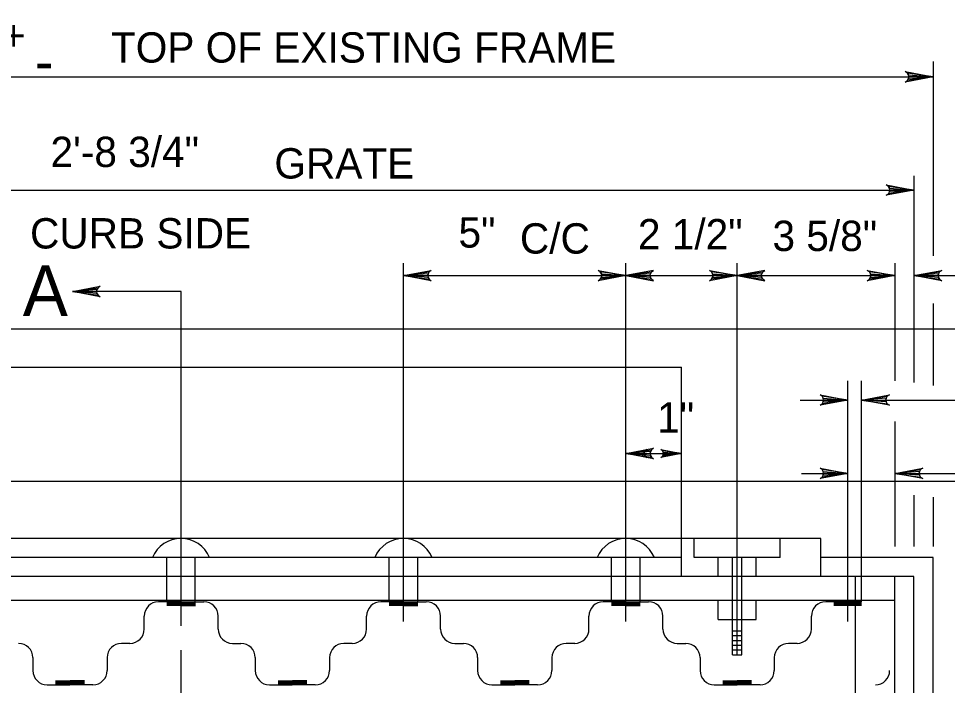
# Model space of a CAD drawing. Extents: x -0.3 to 6.9, y -6.5 to 3.5.
# Drawn here: x 2.615 to 4.451, y 2.033 to 3.352 of the extents above; entities that cross this region are included whole.
import ezdxf

# ---------------------------------------------------------------- set-up
doc = ezdxf.new("R2010")
doc.units = 0
for name, color, linetype in [('DETL-DIMS', 7, 'Continuous'), ('DETL-LINE', 7, 'Continuous'), ('DETL-NOTE', 7, 'Continuous'), ('DETL-PATT', 7, 'Continuous')]:
    doc.layers.add(name, color=color, linetype=linetype)

msp = doc.modelspace()

# ---------------------------------------------------------------- linework, layer by layer
at = {"layer": 'DETL-DIMS'}
for p, q in [((4.4228, 3.2671), (4.4228, 2.8829)), ((1.4487, 3.2371), (4.4228, 3.2371)), ((4.3851, 3.0414), (4.3851, 2.6324)), ((1.4863, 3.013), (4.3851, 3.013)), ((3.3762, 2.1596), (3.3762, 2.8683)), ((3.8157, 2.1596), (3.8157, 2.8683)), ((4.0357, 2.0942), (4.0357, 2.8683)), ((4.3475, 2.8683), (4.3475, 2.6361)), ((3.3762, 2.844), (4.3475, 2.844)), ((4.3851, 2.844), (4.5854, 2.844)), ((2.9366, 2.8125), (2.7219, 2.8125)), ((2.9366, 2.1513), (2.9366, 2.8125)), ((4.4228, 2.789), (4.4228, 2.6269)), ((4.2543, 2.1596), (4.2543, 2.6361)), ((4.2816, 2.199), (4.2816, 2.6361)), ((4.1604, 2.5978), (4.2543, 2.5978)), ((4.2816, 2.5978), (4.6336, 2.5978)), ((4.3475, 2.5551), (4.3475, 2.3085)), ((3.8157, 2.4921), (3.9258, 2.4921)), ((4.1627, 2.4529), (4.2543, 2.4529)), ((4.3475, 2.4529), (4.6516, 2.4529)), ((4.3851, 2.4096), (4.3851, 2.3085)), ((4.4228, 2.4059), (4.4228, 2.3085)), ((2.9366, 1.6956), (2.9366, 2.1031))]:
    msp.add_line(p, q, dxfattribs=at)
for points in [[(4.4228, 3.2371), (4.3679, 3.2268), (4.3722, 3.2297), (4.3743, 3.2334), (4.375, 3.2371), (4.3743, 3.2408), (4.3722, 3.2445), (4.3679, 3.2474), (4.4228, 3.2371), (4.3722, 3.2445), (4.3743, 3.2408), (4.4228, 3.2371), (4.375, 3.2371), (4.3743, 3.2334), (4.4228, 3.2371), (4.3722, 3.2297)], [(4.4228, 3.2371), (4.3679, 3.2268), (4.3722, 3.2297), (4.3743, 3.2334), (4.375, 3.2371), (4.3743, 3.2408), (4.3722, 3.2445), (4.3679, 3.2474), (4.4228, 3.2371), (4.3722, 3.2445), (4.3743, 3.2408), (4.4228, 3.2371), (4.375, 3.2371), (4.3743, 3.2334), (4.4228, 3.2371), (4.3722, 3.2297)], [(4.3851, 3.013), (4.3303, 3.0028), (4.3345, 3.0057), (4.3367, 3.0094), (4.3373, 3.013), (4.3367, 3.0167), (4.3345, 3.0204), (4.3303, 3.0233), (4.3851, 3.013), (4.3345, 3.0204), (4.3367, 3.0167), (4.3851, 3.013), (4.3373, 3.013), (4.3367, 3.0094), (4.3851, 3.013), (4.3345, 3.0057)], [(3.3762, 2.844), (3.431, 2.8543), (3.4268, 2.8514), (3.4246, 2.8477), (3.424, 2.844), (3.4246, 2.8403), (3.4268, 2.8367), (3.431, 2.8337), (3.3762, 2.844), (3.4268, 2.8367), (3.4246, 2.8403), (3.3762, 2.844), (3.424, 2.844), (3.4246, 2.8477), (3.3762, 2.844), (3.4268, 2.8514)], [(3.3762, 2.844), (3.431, 2.8543), (3.4268, 2.8514), (3.4246, 2.8477), (3.424, 2.844), (3.4246, 2.8403), (3.4268, 2.8367), (3.431, 2.8337), (3.3762, 2.844), (3.4268, 2.8367), (3.4246, 2.8403), (3.3762, 2.844), (3.424, 2.844), (3.4246, 2.8477), (3.3762, 2.844), (3.4268, 2.8514)], [(3.8157, 2.844), (3.7609, 2.8337), (3.7651, 2.8367), (3.7673, 2.8403), (3.7679, 2.844), (3.7673, 2.8477), (3.7651, 2.8514), (3.7609, 2.8543), (3.8157, 2.844), (3.7651, 2.8514), (3.7673, 2.8477), (3.8157, 2.844), (3.7679, 2.844), (3.7673, 2.8403), (3.8157, 2.844), (3.7651, 2.8367)], [(3.8157, 2.844), (3.8705, 2.8337), (3.8663, 2.8367), (3.8641, 2.8403), (3.8635, 2.844), (3.8641, 2.8477), (3.8663, 2.8514), (3.8705, 2.8543), (3.8157, 2.844), (3.8663, 2.8514), (3.8641, 2.8477), (3.8157, 2.844), (3.8635, 2.844), (3.8641, 2.8403), (3.8157, 2.844), (3.8663, 2.8367)], [(4.0357, 2.844), (3.9808, 2.8337), (3.985, 2.8367), (3.9872, 2.8403), (3.9879, 2.844), (3.9872, 2.8477), (3.985, 2.8514), (3.9808, 2.8543), (4.0357, 2.844), (3.985, 2.8514), (3.9872, 2.8477), (4.0357, 2.844), (3.9879, 2.844), (3.9872, 2.8403), (4.0357, 2.844), (3.985, 2.8367)], [(4.0357, 2.844), (4.0905, 2.8337), (4.0863, 2.8367), (4.0841, 2.8403), (4.0834, 2.844), (4.0841, 2.8477), (4.0863, 2.8514), (4.0905, 2.8543), (4.0357, 2.844), (4.0863, 2.8514), (4.0841, 2.8477), (4.0357, 2.844), (4.0834, 2.844), (4.0841, 2.8403), (4.0357, 2.844), (4.0863, 2.8367)], [(4.3475, 2.844), (4.2927, 2.8337), (4.2969, 2.8367), (4.2991, 2.8403), (4.2997, 2.844), (4.2991, 2.8477), (4.2969, 2.8514), (4.2927, 2.8543), (4.3475, 2.844), (4.2969, 2.8514), (4.2991, 2.8477), (4.3475, 2.844), (4.2997, 2.844), (4.2991, 2.8403), (4.3475, 2.844), (4.2969, 2.8367)], [(4.3475, 2.844), (4.2927, 2.8337), (4.2969, 2.8367), (4.2991, 2.8403), (4.2997, 2.844), (4.2991, 2.8477), (4.2969, 2.8514), (4.2927, 2.8543), (4.3475, 2.844), (4.2969, 2.8514), (4.2991, 2.8477), (4.3475, 2.844), (4.2997, 2.844), (4.2991, 2.8403), (4.3475, 2.844), (4.2969, 2.8367)], [(4.3851, 2.844), (4.44, 2.8543), (4.4357, 2.8514), (4.4336, 2.8477), (4.4329, 2.844), (4.4336, 2.8403), (4.4357, 2.8367), (4.44, 2.8337), (4.3851, 2.844), (4.4357, 2.8367), (4.4336, 2.8403), (4.3851, 2.844), (4.4329, 2.844), (4.4336, 2.8477), (4.3851, 2.844), (4.4357, 2.8514)], [(2.7219, 2.8125), (2.7767, 2.8228), (2.7725, 2.8199), (2.7703, 2.8162), (2.7697, 2.8125), (2.7703, 2.8089), (2.7725, 2.8052), (2.7767, 2.8023), (2.7219, 2.8125), (2.7725, 2.8052), (2.7703, 2.8089), (2.7219, 2.8125), (2.7697, 2.8125), (2.7703, 2.8162), (2.7219, 2.8125), (2.7725, 2.8199)], [(4.2543, 2.5978), (4.1995, 2.5876), (4.2037, 2.5905), (4.2059, 2.5942), (4.2065, 2.5978), (4.2059, 2.6015), (4.2037, 2.6052), (4.1995, 2.6081), (4.2543, 2.5978), (4.2037, 2.6052), (4.2059, 2.6015), (4.2543, 2.5978), (4.2065, 2.5978), (4.2059, 2.5942), (4.2543, 2.5978), (4.2037, 2.5905)], [(4.2816, 2.5978), (4.3364, 2.6081), (4.3322, 2.6052), (4.33, 2.6015), (4.3294, 2.5978), (4.33, 2.5942), (4.3322, 2.5905), (4.3364, 2.5876), (4.2816, 2.5978), (4.3322, 2.5905), (4.33, 2.5942), (4.2816, 2.5978), (4.3294, 2.5978), (4.33, 2.6015), (4.2816, 2.5978), (4.3322, 2.6052)], [(3.8157, 2.4921), (3.8705, 2.5024), (3.8663, 2.4994), (3.8641, 2.4958), (3.8635, 2.4921), (3.8641, 2.4884), (3.8663, 2.4847), (3.8705, 2.4818), (3.8157, 2.4921), (3.8663, 2.4847), (3.8641, 2.4884), (3.8157, 2.4921), (3.8635, 2.4921), (3.8641, 2.4958), (3.8157, 2.4921), (3.8663, 2.4994)], [(3.8157, 2.4921), (3.8568, 2.4998), (3.8537, 2.4976), (3.852, 2.4948), (3.8516, 2.4921), (3.852, 2.4893), (3.8537, 2.4866), (3.8568, 2.4844), (3.8157, 2.4921), (3.8537, 2.4866), (3.852, 2.4893), (3.8157, 2.4921), (3.8516, 2.4921), (3.852, 2.4948), (3.8157, 2.4921), (3.8537, 2.4976)], [(3.9258, 2.4921), (3.8846, 2.4844), (3.8878, 2.4866), (3.8894, 2.4893), (3.8899, 2.4921), (3.8894, 2.4948), (3.8878, 2.4976), (3.8846, 2.4998), (3.9258, 2.4921), (3.8878, 2.4976), (3.8894, 2.4948), (3.9258, 2.4921), (3.8899, 2.4921), (3.8894, 2.4893), (3.9258, 2.4921), (3.8878, 2.4866)], [(3.9258, 2.4921), (3.8846, 2.4844), (3.8878, 2.4866), (3.8894, 2.4893), (3.8899, 2.4921), (3.8894, 2.4948), (3.8878, 2.4976), (3.8846, 2.4998), (3.9258, 2.4921), (3.8878, 2.4976), (3.8894, 2.4948), (3.9258, 2.4921), (3.8899, 2.4921), (3.8894, 2.4893), (3.9258, 2.4921), (3.8878, 2.4866)], [(4.2543, 2.4529), (4.1995, 2.4426), (4.2037, 2.4455), (4.2059, 2.4492), (4.2065, 2.4529), (4.2059, 2.4566), (4.2037, 2.4602), (4.1995, 2.4632), (4.2543, 2.4529), (4.2037, 2.4602), (4.2059, 2.4566), (4.2543, 2.4529), (4.2065, 2.4529), (4.2059, 2.4492), (4.2543, 2.4529), (4.2037, 2.4455)], [(4.2543, 2.4529), (4.1995, 2.4426), (4.2037, 2.4455), (4.2059, 2.4492), (4.2065, 2.4529), (4.2059, 2.4566), (4.2037, 2.4602), (4.1995, 2.4632), (4.2543, 2.4529), (4.2037, 2.4602), (4.2059, 2.4566), (4.2543, 2.4529), (4.2065, 2.4529), (4.2059, 2.4492), (4.2543, 2.4529), (4.2037, 2.4455)], [(4.3475, 2.4529), (4.4023, 2.4632), (4.3981, 2.4602), (4.3959, 2.4566), (4.3953, 2.4529), (4.3959, 2.4492), (4.3981, 2.4455), (4.4023, 2.4426), (4.3475, 2.4529), (4.3981, 2.4455), (4.3959, 2.4492), (4.3475, 2.4529), (4.3953, 2.4529), (4.3959, 2.4566), (4.3475, 2.4529), (4.3981, 2.4602)]]:
    msp.add_lwpolyline(points, dxfattribs=at)
at = {"layer": 'DETL-LINE'}
for p, q in [((4.7992, 2.7381), (1.0722, 2.7381)), ((1.9397, 2.6632), (3.9258, 2.6632)), ((3.9258, 2.2487), (3.9258, 2.6632)), ((4.4981, 2.4369), (1.3734, 2.4369)), ((4.2007, 2.324), (1.6432, 2.324)), ((3.9509, 2.2867), (3.9509, 2.324)), ((4.1204, 2.2867), (4.1204, 2.324)), ((4.2007, 2.2487), (4.2007, 2.324)), ((3.9258, 2.2863), (1.9397, 2.2863)), ((2.9083, 2.199), (2.9083, 2.2864)), ((2.9647, 2.199), (2.9647, 2.2864)), ((3.3479, 2.1992), (3.3479, 2.2865)), ((3.4043, 2.1992), (3.4043, 2.2865)), ((3.7873, 2.199), (3.7873, 2.2864)), ((3.8438, 2.199), (3.8438, 2.2864)), ((4.1204, 2.2867), (3.9509, 2.2867)), ((3.998, 2.2487), (3.998, 2.2867)), ((4.0262, 2.0942), (4.0262, 2.2867)), ((4.0451, 2.0942), (4.0451, 2.2867)), ((4.0733, 2.2487), (4.0733, 2.2867)), ((4.4228, 2.2863), (4.2007, 2.2863)), ((4.4228, -0.189), (4.4228, 2.2863)), ((4.3851, 2.2487), (1.4863, 2.2487)), ((4.2695, -0.1513), (4.2695, 2.2487)), ((4.3475, -0.1513), (4.3475, 2.2487)), ((4.3851, -0.1513), (4.3851, 2.2487)), ((4.3475, 2.2016), (1.524, 2.2016)), ((2.9367, 2.199), (2.892, 2.199)), ((2.9367, 2.1971), (2.9084, 2.1971)), ((2.9367, 2.1952), (2.9084, 2.1952)), ((2.9367, 2.1933), (2.9084, 2.1933)), ((2.9367, 2.1914), (2.9084, 2.1914)), ((2.9368, 2.199), (2.9817, 2.199)), ((2.9368, 2.1971), (2.9649, 2.1971)), ((2.9368, 2.1952), (2.9649, 2.1952)), ((2.9368, 2.1933), (2.9649, 2.1933)), ((2.9368, 2.1914), (2.9649, 2.1914)), ((3.3762, 2.199), (3.3315, 2.199)), ((3.3762, 2.1971), (3.348, 2.1971)), ((3.3762, 2.1952), (3.348, 2.1952)), ((3.3762, 2.1933), (3.348, 2.1933)), ((3.3762, 2.1914), (3.348, 2.1914)), ((3.3763, 2.199), (3.4212, 2.199)), ((3.3763, 2.1971), (3.4044, 2.1971)), ((3.3763, 2.1952), (3.4044, 2.1952)), ((3.3763, 2.1933), (3.4044, 2.1933)), ((3.3763, 2.1914), (3.4044, 2.1914)), ((3.8157, 2.199), (3.771, 2.199)), ((3.8157, 2.1971), (3.7875, 2.1971)), ((3.8157, 2.1952), (3.7875, 2.1952)), ((3.8157, 2.1933), (3.7875, 2.1933)), ((3.8157, 2.1914), (3.7875, 2.1914)), ((3.8159, 2.199), (3.8607, 2.199)), ((3.8159, 2.1971), (3.844, 2.1971)), ((3.8159, 2.1952), (3.844, 2.1952)), ((3.8159, 2.1933), (3.844, 2.1933)), ((3.8159, 2.1914), (3.844, 2.1914)), ((3.998, 2.1636), (3.998, 2.2016)), ((4.0733, 2.1636), (4.0733, 2.2016)), ((4.2816, 2.199), (4.2106, 2.199)), ((4.2816, 2.1971), (4.227, 2.1971)), ((4.2816, 2.1952), (4.227, 2.1952)), ((4.2816, 2.1933), (4.227, 2.1933)), ((4.2816, 2.1914), (4.227, 2.1914)), ((2.8637, 2.1448), (2.8637, 2.1707)), ((3.0099, 2.1448), (3.0099, 2.1707)), ((3.3033, 2.1448), (3.3033, 2.1707)), ((3.4494, 2.1448), (3.4494, 2.1707)), ((3.7428, 2.1448), (3.7428, 2.1707)), ((3.889, 2.1448), (3.889, 2.1707)), ((4.1823, 2.1448), (4.1823, 2.1707)), ((3.998, 2.1636), (4.0733, 2.1636)), ((2.8355, 2.1166), (2.8187, 2.1166)), ((3.0382, 2.1166), (3.0549, 2.1166)), ((3.275, 2.1166), (3.2583, 2.1166)), ((3.4777, 2.1166), (3.4945, 2.1166)), ((3.7146, 2.1166), (3.6978, 2.1166)), ((3.9172, 2.1166), (3.934, 2.1166)), ((4.1541, 2.1166), (4.1373, 2.1166)), ((4.0262, 2.0942), (4.0451, 2.0942)), ((2.6436, 2.0884), (2.6436, 2.0629)), ((2.7905, 2.0884), (2.7905, 2.0629)), ((3.0832, 2.0884), (3.0832, 2.0629)), ((3.23, 2.0884), (3.23, 2.0629)), ((3.5227, 2.0884), (3.5227, 2.0629)), ((3.6695, 2.0884), (3.6695, 2.0629)), ((3.9622, 2.0884), (3.9622, 2.0629)), ((4.1091, 2.0884), (4.1091, 2.0629)), ((2.6887, 2.0422), (2.7169, 2.0422)), ((2.6887, 2.0403), (2.7169, 2.0403)), ((2.6887, 2.0384), (2.7169, 2.0384)), ((2.7455, 2.0422), (2.7172, 2.0422)), ((2.7455, 2.0403), (2.7172, 2.0403)), ((2.7455, 2.0384), (2.7172, 2.0384)), ((3.1282, 2.0422), (3.1564, 2.0422)), ((3.1282, 2.0403), (3.1564, 2.0403)), ((3.1282, 2.0384), (3.1564, 2.0384)), ((3.185, 2.0422), (3.1568, 2.0422)), ((3.185, 2.0403), (3.1568, 2.0403)), ((3.185, 2.0384), (3.1568, 2.0384)), ((3.5677, 2.0422), (3.596, 2.0422)), ((3.5677, 2.0403), (3.596, 2.0403)), ((3.5677, 2.0384), (3.596, 2.0384)), ((3.6245, 2.0422), (3.5963, 2.0422)), ((3.6245, 2.0403), (3.5963, 2.0403)), ((3.6245, 2.0384), (3.5963, 2.0384)), ((4.0072, 2.0422), (4.0355, 2.0422)), ((4.0072, 2.0403), (4.0355, 2.0403)), ((4.0072, 2.0384), (4.0355, 2.0384)), ((4.0641, 2.0422), (4.0358, 2.0422)), ((4.0641, 2.0403), (4.0358, 2.0403)), ((4.0641, 2.0384), (4.0358, 2.0384)), ((2.6719, 2.0346), (2.7169, 2.0346)), ((2.6887, 2.0365), (2.7169, 2.0365)), ((2.7455, 2.0365), (2.7172, 2.0365)), ((2.7623, 2.0346), (2.7172, 2.0346)), ((3.1114, 2.0346), (3.1564, 2.0346)), ((3.1282, 2.0365), (3.1564, 2.0365)), ((3.185, 2.0365), (3.1568, 2.0365)), ((3.2018, 2.0346), (3.1568, 2.0346)), ((3.5509, 2.0346), (3.596, 2.0346)), ((3.5677, 2.0365), (3.596, 2.0365)), ((3.6245, 2.0365), (3.5963, 2.0365)), ((3.6413, 2.0346), (3.5963, 2.0346)), ((3.9905, 2.0346), (4.0355, 2.0346)), ((4.0072, 2.0365), (4.0355, 2.0365)), ((4.0641, 2.0365), (4.0358, 2.0365)), ((4.0808, 2.0346), (4.0358, 2.0346))]:
    msp.add_line(p, q, dxfattribs=at)
for centre, radius, start, end in [((2.9365, 2.2629), 0.0612, 22.6199, 157.3801), ((3.3761, 2.263), 0.0612, 22.6199, 157.3801), ((3.8155, 2.2629), 0.0612, 22.6199, 157.3801), ((2.892, 2.1707), 0.0282, 90, 180), ((2.9817, 2.1707), 0.0282, 0, 90), ((3.3315, 2.1707), 0.0282, 90, 180), ((3.4212, 2.1707), 0.0282, 0, 90), ((3.771, 2.1707), 0.0282, 90, 180), ((3.8607, 2.1707), 0.0282, 0, 90), ((4.2106, 2.1707), 0.0282, 90, 180), ((2.8355, 2.1448), 0.0282, 270, 0), ((3.0382, 2.1448), 0.0282, 180, 270), ((3.275, 2.1448), 0.0282, 270, 0), ((3.4777, 2.1448), 0.0282, 180, 270), ((3.7146, 2.1448), 0.0282, 270, 0), ((3.9172, 2.1448), 0.0282, 180, 270), ((4.1541, 2.1448), 0.0282, 270, 0), ((2.6154, 2.0884), 0.0282, 0, 90), ((2.8187, 2.0884), 0.0282, 90, 180), ((3.0549, 2.0884), 0.0282, 0, 90), ((3.2583, 2.0884), 0.0282, 90, 180), ((3.4945, 2.0884), 0.0282, 0, 90), ((3.6978, 2.0884), 0.0282, 90, 180), ((3.934, 2.0884), 0.0282, 0, 90), ((4.1373, 2.0884), 0.0282, 90, 180), ((2.6719, 2.0629), 0.0282, 180, 270), ((2.7623, 2.0629), 0.0282, 270, 0), ((3.1114, 2.0629), 0.0282, 180, 270), ((3.2018, 2.0629), 0.0282, 270, 0), ((3.5509, 2.0629), 0.0282, 180, 270), ((3.6413, 2.0629), 0.0282, 270, 0), ((3.9905, 2.0629), 0.0282, 180, 270), ((4.0808, 2.0629), 0.0282, 270, 0), ((4.3088, 2.0629), 0.0282, 270, 0)]:
    msp.add_arc(centre, radius, start, end, dxfattribs=at)
at = {"layer": 'DETL-PATT'}
for p, q in [((4.0262, 2.1413), (4.0451, 2.1413)), ((4.0262, 2.1319), (4.0451, 2.1319)), ((4.0262, 2.1225), (4.0451, 2.1225)), ((4.0262, 2.1131), (4.0451, 2.1131)), ((4.0262, 2.1036), (4.0451, 2.1036))]:
    msp.add_line(p, q, dxfattribs=at)

# ---------------------------------------------------------------- texts
at = {"layer": 'DETL-NOTE'}
for s, height, p in [('2\'-9 7/16"+', 0.06, (2.2441, 3.2891)), ('TOP OF EXISTING FRAME', 0.06, (2.798, 3.2652)), ('-', 0.0824, (2.6479, 3.2266)), ('2\'-8 3/4"', 0.06, (2.6785, 3.0587)), ('GRATE', 0.06, (3.121, 3.036)), ('CURB SIDE', 0.06, (2.6381, 2.8976)), ('5"', 0.06, (3.4849, 2.8994)), ('2 1/2"', 0.06, (3.8395, 2.8959)), ('3 5/8"', 0.06, (4.1054, 2.8926)), ('C/C', 0.06, (3.6063, 2.8875)), ('A', 0.1, (2.6237, 2.764)), ('1"', 0.06, (3.8776, 2.5335))]:
    msp.add_text(s, height=height, dxfattribs=at).set_placement(p)

doc.saveas('drawing.dxf')
